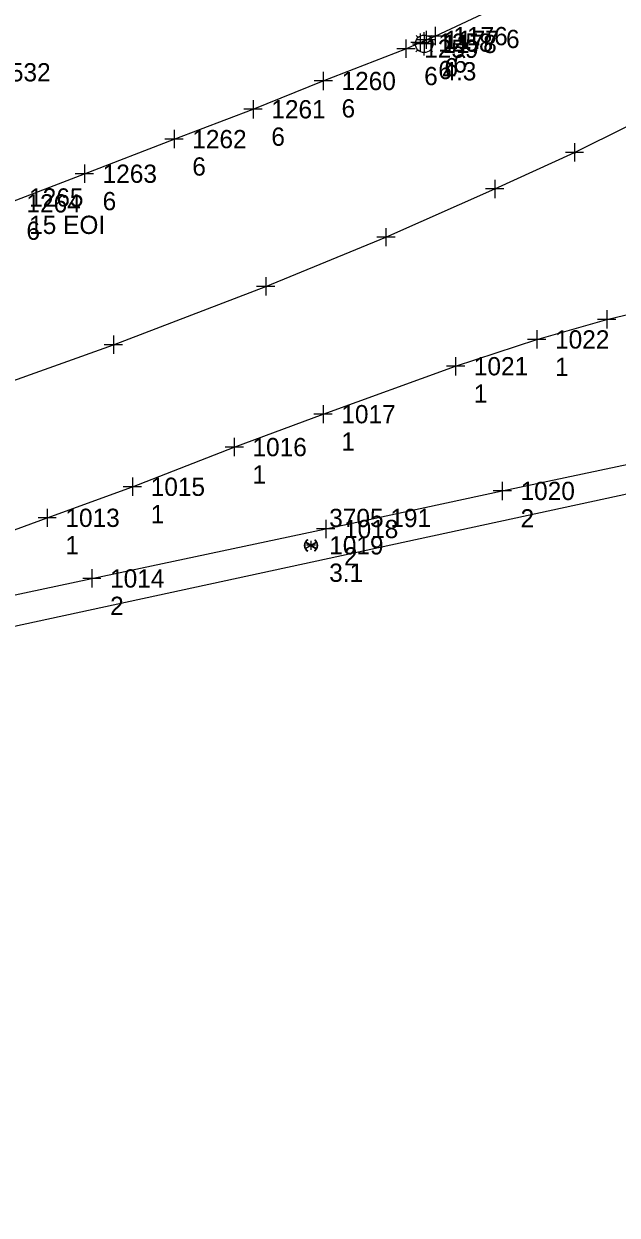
# Model space of a CAD drawing. Extents: x 352921 to 392463, y 10654752 to 10749237.
# Drawn here: x 389703.7 to 389866.1, y 10658730.9 to 10659057.1 of the extents above; entities that cross this region are included whole.
import ezdxf

# ---------------------------------------------------------------- set-up
doc = ezdxf.new("R2010")
doc.units = 0
for name, color, linetype in [('GAS', 7, 'Continuous'), ('GAS_#', 7, 'Continuous'), ('GAS_DES', 7, 'Continuous'), ('GAS_SPOT', 7, 'Continuous'), ('LIMITS', 7, 'Continuous'), ('TC', 7, 'Continuous'), ('UE', 7, 'Continuous'), ('UE_#', 7, 'Continuous'), ('UE_DES', 7, 'Continuous'), ('UE_ELEV', 7, 'Continuous'), ('UE_SPOT', 7, 'Continuous'), ('W_#', 7, 'Continuous'), ('W_DES', 7, 'Continuous'), ('W_ELEV', 7, 'Continuous'), ('W_SPOT', 7, 'Continuous'), ('WATER', 7, 'Continuous'), ('WW_#', 7, 'Continuous'), ('WW_DES', 7, 'Continuous')]:
    doc.layers.add(name, color=color, linetype=linetype)

msp = doc.modelspace()

# ---------------------------------------------------------------- linework, layer by layer
at = {"layer": 'GAS'}
msp.add_lwpolyline([(389640.48, 10659008.29), (389644.1, 10658979.77), (389649.59, 10658942.02), (389651.76, 10658932.84), (389658.87, 10658891.89), (389671.21, 10658894.35), (389722.3, 10658905.22), (389786.32, 10658918.77), (389834.65, 10658929.18), (389900.61, 10658943.19)], dxfattribs=at)
at = {"layer": 'GAS_SPOT'}
for p, q in [((389834.65, 10658931.68), (389834.65, 10658926.68)), ((389837.15, 10658929.18), (389832.15, 10658929.18)), ((389786.32, 10658921.27), (389786.32, 10658916.27)), ((389788.82, 10658918.77), (389783.82, 10658918.77)), ((389722.3, 10658907.72), (389722.3, 10658902.72)), ((389724.8, 10658905.22), (389719.8, 10658905.22))]:
    msp.add_line(p, q, dxfattribs=at)
at = {"layer": 'LIMITS'}
msp.add_line((388080.78, 10658541.98), (390234.87, 10659007.56), dxfattribs=at)
at = {"layer": 'TC'}
msp.add_lwpolyline([(389382.38, 10658875.13), (389415.42, 10658882.74), (389442.44, 10658888.95), (389467.77, 10658894.86), (389469.49, 10658895.35), (389478.01, 10658897.46), (389498.66, 10658902.5), (389524.47, 10658908.86), (389546.78, 10658916.02), (389571.66, 10658923.73), (389597.82, 10658930.95), (389611.7, 10658934.68), (389613.56, 10658935.16), (389629.56, 10658938.56), (389659.27, 10658946.57), (389696.73, 10658957.96), (389728.19, 10658969.24), (389769.89, 10658985.21), (389802.81, 10658998.69), (389832.57, 10659011.9), (389854.42, 10659021.88), (389868.94, 10659029.08)], dxfattribs=at)
at = {"layer": 'UE'}
for p, q in [((389811.59, 10659053.34), (389811.05, 10659053.88)), ((389813.26, 10659054.02), (389813.26, 10659054.78)), ((389814.93, 10659053.34), (389815.47, 10659053.88)), ((389810.09, 10659051.67), (389810.86, 10659051.67)), ((389815.66, 10659051.67), (389816.43, 10659051.67)), ((389811, 10659049.41), (389811.54, 10659049.95)), ((389813.26, 10659048.45), (389813.26, 10659049.22)), ((389815.53, 10659049.4), (389814.99, 10659049.94))]:
    msp.add_line(p, q, dxfattribs=at)
msp.add_lwpolyline([(389699.39, 10659007.95), (389720.25, 10659016.06), (389744.79, 10659025.54), (389766.43, 10659033.71), (389785.65, 10659041.45), (389808.27, 10659050.3), (389812.14, 10659051.96), (389813.83, 10659052.73), (389816.26, 10659053.74), (389830.68, 10659060.47)], dxfattribs=at)
msp.add_circle((389813.26, 10659051.62), 2.4, dxfattribs=at)
msp.add_circle((389813.26, 10659051.62), 2.4, dxfattribs=at)
at = {"layer": 'UE_SPOT'}
for p, q in [((389812.14, 10659054.46), (389812.14, 10659049.46)), ((389813.26, 10659054.12), (389813.26, 10659049.12)), ((389818.76, 10659053.74), (389813.76, 10659053.74)), ((389813.83, 10659055.23), (389813.83, 10659050.23)), ((389816.26, 10659056.24), (389816.26, 10659051.24)), ((389808.27, 10659052.8), (389808.27, 10659047.8)), ((389814.64, 10659051.96), (389809.64, 10659051.96)), ((389815.76, 10659051.62), (389810.76, 10659051.62)), ((389816.33, 10659052.73), (389811.33, 10659052.73)), ((389810.77, 10659050.3), (389805.77, 10659050.3)), ((389785.65, 10659043.95), (389785.65, 10659038.95)), ((389788.15, 10659041.45), (389783.15, 10659041.45)), ((389766.43, 10659036.21), (389766.43, 10659031.21)), ((389768.93, 10659033.71), (389763.93, 10659033.71)), ((389744.79, 10659028.04), (389744.79, 10659023.04)), ((389747.29, 10659025.54), (389742.29, 10659025.54)), ((389854.42, 10659024.38), (389854.42, 10659019.38)), ((389856.92, 10659021.88), (389851.92, 10659021.88)), ((389720.25, 10659018.56), (389720.25, 10659013.56)), ((389722.75, 10659016.06), (389717.75, 10659016.06)), ((389835.07, 10659011.9), (389830.07, 10659011.9)), ((389832.57, 10659014.4), (389832.57, 10659009.4)), ((389805.31, 10658998.69), (389800.31, 10658998.69)), ((389802.81, 10659001.19), (389802.81, 10658996.19)), ((389772.39, 10658985.21), (389767.39, 10658985.21)), ((389769.89, 10658987.71), (389769.89, 10658982.71)), ((389730.69, 10658969.24), (389725.69, 10658969.24)), ((389728.19, 10658971.74), (389728.19, 10658966.74))]:
    msp.add_line(p, q, dxfattribs=at)
at = {"layer": 'W_SPOT'}
for p, q in [((389863.26, 10658978.67), (389863.26, 10658973.67)), ((389865.76, 10658976.17), (389860.76, 10658976.17)), ((389844.1, 10658973.18), (389844.1, 10658968.18)), ((389846.6, 10658970.68), (389841.6, 10658970.68)), ((389821.86, 10658965.84), (389821.86, 10658960.84)), ((389824.36, 10658963.34), (389819.36, 10658963.34)), ((389785.59, 10658952.71), (389785.59, 10658947.71)), ((389788.09, 10658950.21), (389783.09, 10658950.21)), ((389761.27, 10658943.7), (389761.27, 10658938.7)), ((389763.77, 10658941.2), (389758.77, 10658941.2)), ((389735.91, 10658930.33), (389730.91, 10658930.33)), ((389733.41, 10658932.83), (389733.41, 10658927.83)), ((389710.06, 10658924.33), (389710.06, 10658919.33)), ((389712.56, 10658921.83), (389707.56, 10658921.83)), ((389783.53, 10658914.29), (389781.03, 10658914.29)), ((389782.28, 10658915.54), (389782.28, 10658913.04))]:
    msp.add_line(p, q, dxfattribs=at)
at = {"layer": 'WATER'}
for p, q in [((389780.72, 10658913.43), (389783.85, 10658915.14)), ((389780.74, 10658915.18), (389783.81, 10658913.4)), ((389780.75, 10658913.52), (389782.14, 10658914.28)), ((389782.14, 10658914.28), (389780.77, 10658915.08)), ((389780.82, 10658913.4), (389782.29, 10658914.2)), ((389782.29, 10658914.36), (389780.84, 10658915.2)), ((389781.4, 10658915.75), (389781.32, 10658915.87)), ((389783.76, 10658915.17), (389782.29, 10658914.36)), ((389782.29, 10658914.2), (389783.73, 10658913.36)), ((389783.82, 10658915.04), (389782.43, 10658914.28)), ((389782.43, 10658914.28), (389783.81, 10658913.49)), ((389783.42, 10658915.76), (389783.33, 10658915.64)), ((389783.24, 10658912.85), (389783.32, 10658912.74))]:
    msp.add_line(p, q, dxfattribs=at)
msp.add_lwpolyline([(389613.74, 10658975.23), (389618.81, 10658936.27), (389621.32, 10658921.95), (389626.63, 10658893.57), (389631.24, 10658894.65), (389667.25, 10658906.16), (389710.06, 10658921.83), (389733.41, 10658930.33), (389761.27, 10658941.2), (389785.59, 10658950.21), (389821.86, 10658963.34), (389844.1, 10658970.68), (389863.26, 10658976.17), (389888.27, 10658982.2)], dxfattribs=at)
for centre, radius, start, end in [((389782.29, 10658914.28), 1.86, 121.3633, 239.9103), ((389782.28, 10658914.29), 1.79, 121.3633, 239.9103), ((389782.29, 10658914.28), 1.71, 152.3305, 206.3323), ((389782.29, 10658914.28), 1.71, 211.1083, 239.9103), ((389782.29, 10658914.28), 1.71, 121.3633, 147.5545), ((389782.29, 10658914.28), 1.71, 303.5829, 327.5218), ((389782.28, 10658914.29), 1.79, 303.5829, 52.4874), ((389782.29, 10658914.28), 1.86, 303.5829, 52.4874), ((389782.29, 10658914.28), 1.71, 31.1083, 52.4874), ((389782.29, 10658914.28), 1.71, 332.2978, 26.3323)]:
    msp.add_arc(centre, radius, start, end, dxfattribs=at)

# ---------------------------------------------------------------- texts
at = {"layer": 'GAS_#'}
for s, p in [('1020', (389839.65, 10658926.68)), ('1018', (389791.32, 10658916.27)), ('1014', (389727.3, 10658902.72))]:
    msp.add_text(s, height=5, dxfattribs=at).set_placement(p)
at = {"layer": 'GAS_DES'}
for p in [(389839.65, 10658919.18), (389791.32, 10658908.77), (389727.3, 10658895.22)]:
    msp.add_text('2', height=5, dxfattribs=at).set_placement(p)
at = {"layer": 'UE_#'}
for s, height, p in [('1258', 5, (389817.14, 10659049.46)), ('1178', 5, (389818.26, 10659049.12)), ('1177', 5, (389818.83, 10659050.23)), ('1176', 5, (389821.26, 10659051.24)), ('1259', 5, (389813.27, 10659047.8)), ('1260', 5, (389790.65, 10659038.95)), ('1261', 5, (389771.43, 10659031.21)), ('1262', 5, (389749.79, 10659023.04)), ('1245', 0.15, (389854.58, 10659021.81)), ('1263', 5, (389725.25, 10659013.56)), ('1246', 0.15, (389832.72, 10659011.82)), ('1264', 5, (389704.39, 10659005.45)), ('1247', 0.15, (389802.96, 10658998.61)), ('1248', 0.15, (389770.04, 10658985.13)), ('1249', 0.15, (389728.34, 10658969.16))]:
    msp.add_text(s, height=height, dxfattribs=at).set_placement(p)
at = {"layer": 'UE_DES'}
for s, height, p in [('6', 5, (389835.68, 10659050.47)), ('6', 5, (389818.83, 10659042.73)), ('6', 5, (389821.26, 10659043.74)), ('6', 5, (389813.27, 10659040.3)), ('6', 5, (389817.14, 10659041.96)), ('4.3', 5, (389818.26, 10659041.62)), ('6', 5, (389790.65, 10659031.45)), ('6', 5, (389771.43, 10659023.71)), ('13', 0.15, (389854.58, 10659021.58)), ('6', 5, (389749.79, 10659015.54)), ('13', 0.15, (389832.72, 10659011.6)), ('6', 5, (389725.25, 10659006.06)), ('6', 5, (389704.39, 10658997.95)), ('13', 0.15, (389802.96, 10658998.39)), ('13', 0.15, (389770.04, 10658984.91)), ('13', 0.15, (389728.34, 10658968.94))]:
    msp.add_text(s, height=height, dxfattribs=at).set_placement(p)
at = {"layer": 'UE_ELEV'}
for s, height, p in [('3704.532', 5, (389683.13, 10659041.34)), ('3705.936', 0.15, (389854.58, 10659022.03)), ('3705.963', 0.15, (389832.72, 10659012.05)), ('3705.905', 0.15, (389802.96, 10658998.84)), ('3705.769', 0.15, (389770.04, 10658985.36)), ('3705.658', 0.15, (389728.34, 10658969.39))]:
    msp.add_text(s, height=height, dxfattribs=at).set_placement(p)
at = {"layer": 'W_#'}
for s, p in [('1022', (389849.1, 10658968.18)), ('1021', (389826.86, 10658960.84)), ('1017', (389790.59, 10658947.71)), ('1016', (389766.27, 10658938.7)), ('1015', (389738.41, 10658927.83)), ('1013', (389715.06, 10658919.33)), ('1019', (389787.28, 10658911.79))]:
    msp.add_text(s, height=5, dxfattribs=at).set_placement(p)
at = {"layer": 'W_DES'}
for s, p in [('1', (389849.1, 10658960.68)), ('1', (389826.86, 10658953.34)), ('1', (389790.59, 10658940.21)), ('1', (389766.27, 10658931.2)), ('1', (389738.41, 10658920.33)), ('1', (389715.06, 10658911.83)), ('3.1', (389787.28, 10658904.29))]:
    msp.add_text(s, height=5, dxfattribs=at).set_placement(p)
at = {"layer": 'W_ELEV'}
msp.add_text('3705.191', height=5, dxfattribs=at).set_placement((389787.28, 10658919.29))
at = {"layer": 'WW_#'}
msp.add_text('1265', height=5, dxfattribs=at).set_placement((389705.13, 10659007.06))
at = {"layer": 'WW_DES'}
msp.add_text('15 EOI', height=5, dxfattribs=at).set_placement((389705.13, 10658999.56))

doc.saveas('drawing.dxf')
